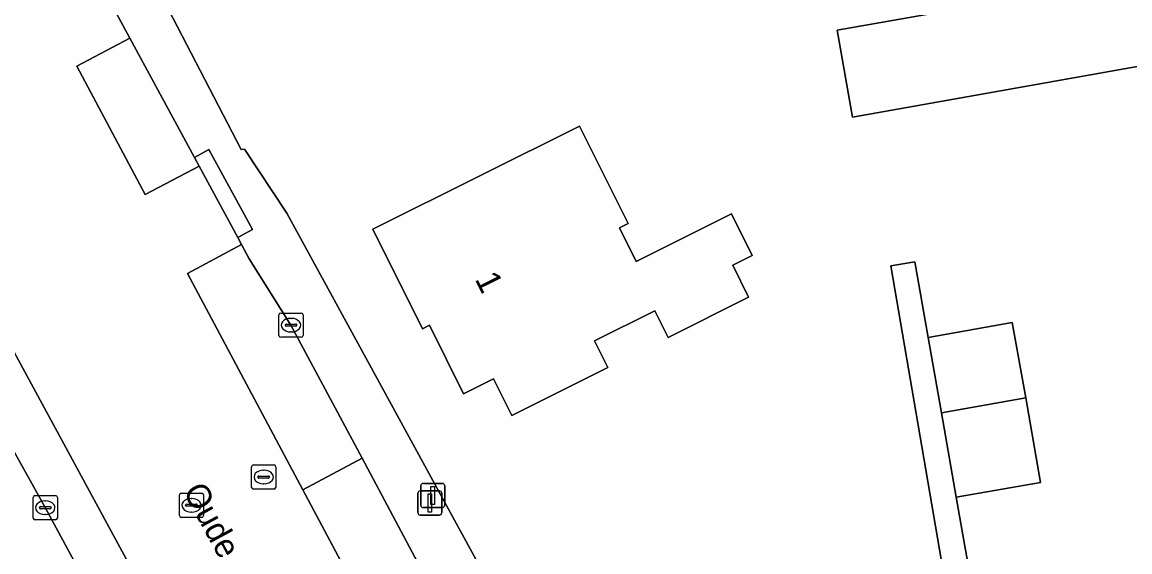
# Model space of a CAD drawing. Extents: x 162879 to 165540, y 384011 to 385181.
# Drawn here: x 164236.51 to 164282.3, y 384276.82 to 384298.69 of the extents above; entities that cross this region are included whole.
import ezdxf

# ---------------------------------------------------------------- set-up
doc = ezdxf.new("R2010")
doc.units = 0
for name, color, linetype in [('IMGEO_Erf', 7, 'Continuous'), ('IMGEO_Kolk', 7, 'Continuous'), ('IMGEO_Lichtmast', 7, 'Continuous'), ('IMGEO_Openbare_ruimte_label', 7, 'Continuous'), ('IMGEO_OVBaan_gesloten', 7, 'Continuous'), ('IMGEO_Pand', 7, 'Continuous'), ('IMGEO_Pand_nummerreeks', 7, 'Continuous'), ('IMGEO_Parkeervlak_gesloten', 7, 'Continuous'), ('IMGEO_Rijbaan_lokaal_gesloten', 7, 'Continuous'), ('IMGEO_Rioolput', 7, 'Continuous'), ('IMGEO_Voetpad_open', 7, 'Continuous')]:
    doc.layers.add(name, color=color, linetype=linetype)

msp = doc.modelspace()

# ---------------------------------------------------------------- linework, layer by layer
at = {"layer": 'IMGEO_Erf'}
for points in [[(164241.621, 384301.03), (164245.563, 384293.433), (164245.698, 384293.443), (164247.447, 384290.807), (164265.625, 384257.55), (164277.401, 384259.579), (164272.425, 384288.625), (164273.405, 384288.793), (164273.957, 384285.675), (164277.428, 384286.289), (164277.994, 384283.174), (164278.603, 384279.686), (164275.126, 384279.071), (164276.143, 384273.323), (164279.613, 384273.937), (164280.199, 384270.625), (164280.785, 384267.312), (164281.351, 384264.111), (164277.882, 384263.498), (164278.541, 384259.775), (164297.909, 384263.112)], [(164283.929, 384297.094), (164270.831, 384294.777), (164270.198, 384298.357), (164279.159, 384299.942)]]:
    msp.add_lwpolyline(points, dxfattribs=at)
msp.add_lwpolyline([(164259.556, 384294.396), (164261.556, 384290.377), (164261.197, 384290.198), (164261.886, 384288.812), (164265.832, 384290.775), (164266.687, 384289.057), (164265.882, 384288.656), (164266.542, 384287.33), (164263.209, 384285.672), (164262.659, 384286.776), (164260.171, 384285.538), (164260.723, 384284.431), (164256.747, 384282.452), (164255.994, 384283.965), (164254.753, 384283.347), (164253.346, 384286.175), (164253.059, 384286.033), (164251.013, 384290.145), (164255.481, 384292.369)], close=True, dxfattribs=at)
at = {"layer": 'IMGEO_Kolk'}
for p, q in [((164247.123, 384285.753), (164247.123, 384286.605)), ((164247.198, 384286.679), (164248.05, 384286.679)), ((164247.611, 384286.459), (164247.636, 384286.459)), ((164248.124, 384286.605), (164248.124, 384285.753)), ((164247.382, 384286.173), (164247.382, 384286.185)), ((164247.82, 384286.136), (164247.422, 384286.136)), ((164247.425, 384286.222), (164247.823, 384286.222)), ((164247.634, 384285.899), (164247.609, 384285.899)), ((164247.866, 384286.185), (164247.866, 384286.173)), ((164248.05, 384285.679), (164247.198, 384285.679)), ((164236.967, 384278.213), (164236.967, 384279.065)), ((164237.042, 384279.139), (164237.894, 384279.139)), ((164237.968, 384279.065), (164237.968, 384278.213)), ((164237.226, 384278.633), (164237.226, 384278.645)), ((164237.664, 384278.596), (164237.266, 384278.596)), ((164237.269, 384278.682), (164237.667, 384278.682)), ((164237.455, 384278.919), (164237.48, 384278.919)), ((164237.71, 384278.645), (164237.71, 384278.633)), ((164237.894, 384278.139), (164237.042, 384278.139)), ((164237.478, 384278.359), (164237.453, 384278.359))]:
    msp.add_line(p, q, dxfattribs=at)
for points in [[(164247.123, 384285.753), (164247.123, 384286.605)], [(164247.198, 384286.679), (164248.05, 384286.679)], [(164248.124, 384286.605), (164248.124, 384285.753)], [(164248.05, 384285.679), (164247.198, 384285.679)], [(164236.967, 384278.213), (164236.967, 384279.065)], [(164237.042, 384279.139), (164237.894, 384279.139)], [(164237.968, 384279.065), (164237.968, 384278.213)], [(164237.894, 384278.139), (164237.042, 384278.139)]]:
    msp.add_lwpolyline(points, dxfattribs=at)
for centre, radius, start, end in [((164247.2, 384286.603), 0.0765, 91.552, 178.448), ((164247.2, 384286.603), 0.0765, 91.552, 178.448), ((164248.048, 384286.603), 0.0765, 1.552, 88.448), ((164248.048, 384286.603), 0.0765, 1.552, 88.448), ((164247.422, 384286.182), 0.0403, 85.8775, 175.7526), ((164247.419, 384286.172), 0.0366, 178.938, 274.7102), ((164247.823, 384286.179), 0.043, 264.8664, 352.4533), ((164247.827, 384286.184), 0.0386, 1.7309, 96.639), ((164247.2, 384285.755), 0.0765, 181.552, 268.448), ((164247.2, 384285.755), 0.0765, 181.552, 268.448), ((164248.048, 384285.755), 0.0765, 271.552, 358.448), ((164248.048, 384285.755), 0.0765, 271.552, 358.448), ((164237.044, 384279.063), 0.0765, 91.552, 178.448), ((164237.044, 384279.063), 0.0765, 91.552, 178.448), ((164237.892, 384279.063), 0.0765, 1.552, 88.448), ((164237.892, 384279.063), 0.0765, 1.552, 88.448), ((164237.266, 384278.642), 0.0403, 85.8775, 175.7526), ((164237.263, 384278.632), 0.0366, 178.938, 274.7102), ((164237.667, 384278.639), 0.043, 264.8664, 352.4533), ((164237.671, 384278.644), 0.0386, 1.7309, 96.639), ((164237.044, 384278.215), 0.0765, 181.552, 268.448), ((164237.044, 384278.215), 0.0765, 181.552, 268.448), ((164237.892, 384278.215), 0.0765, 271.552, 358.448), ((164237.892, 384278.215), 0.0765, 271.552, 358.448)]:
    msp.add_arc(centre, radius, start, end, dxfattribs=at)
for centre, major_axis, ratio, start_param, end_param in [((164247.61, 384286.179), (-0.387, 0.002), 0.722429, 4.712389, 7.853982), ((164247.635, 384286.179), (-0.39, 0.002), 0.717154, 1.570796, 4.712389), ((164237.454, 384278.639), (-0.387, 0.002), 0.722429, 4.712389, 7.853982), ((164237.479, 384278.639), (-0.39, 0.002), 0.717154, 1.570796, 4.712389)]:
    msp.add_ellipse(centre, major_axis=major_axis, ratio=ratio, start_param=start_param, end_param=end_param, dxfattribs=at)
at = {"layer": 'IMGEO_Lichtmast'}
for p, q in [((164252.987, 384278.74), (164252.987, 384279.54)), ((164252.987, 384279.54), (164252.987, 384278.74)), ((164253.087, 384279.64), (164253.877, 384279.64)), ((164253.877, 384279.64), (164253.087, 384279.64)), ((164253.977, 384279.54), (164253.977, 384278.74)), ((164253.977, 384278.74), (164253.977, 384279.54)), ((164252.868, 384278.435), (164252.868, 384279.235)), ((164252.868, 384279.235), (164252.868, 384278.435)), ((164252.968, 384279.335), (164253.758, 384279.335)), ((164253.758, 384279.335), (164252.968, 384279.335)), ((164253.858, 384279.235), (164253.858, 384278.435)), ((164253.858, 384278.435), (164253.858, 384279.235)), ((164253.877, 384278.64), (164253.087, 384278.64)), ((164253.087, 384278.64), (164253.877, 384278.64)), ((164253.758, 384278.335), (164252.968, 384278.335)), ((164252.968, 384278.335), (164253.758, 384278.335))]:
    msp.add_line(p, q, dxfattribs=at)
for points in [[(164253.407, 384279.515), (164253.557, 384279.515), (164253.557, 384278.765), (164253.407, 384278.765), (164253.407, 384279.515)], [(164253.288, 384279.21), (164253.438, 384279.21), (164253.438, 384278.46), (164253.288, 384278.46), (164253.288, 384279.21)]]:
    msp.add_lwpolyline(points, dxfattribs=at)
for centre, start, end in [((164253.087, 384279.54), 90, 180), ((164253.087, 384279.54), 90, 180), ((164253.877, 384279.54), 0, 90), ((164253.877, 384279.54), 360, 90), ((164252.968, 384279.235), 90, 180), ((164252.968, 384279.235), 90, 180), ((164253.758, 384279.235), 0, 90), ((164253.758, 384279.235), 360, 90), ((164253.087, 384278.74), 180, 270), ((164253.087, 384278.74), 180, 270), ((164253.877, 384278.74), 270, 0), ((164253.877, 384278.74), 270, 0), ((164252.968, 384278.435), 180, 270), ((164252.968, 384278.435), 180, 270), ((164253.758, 384278.435), 270, 0), ((164253.758, 384278.435), 270, 0)]:
    msp.add_arc(centre, 0.1, start, end, dxfattribs=at)
at = {"layer": 'IMGEO_OVBaan_gesloten'}
msp.add_lwpolyline([(164250.573, 384280.685), (164248.108, 384279.38), (164259.664, 384257.72), (164269.773, 384244.273), (164268.442, 384246.955), (164266.854, 384250), (164265.912, 384251.805), (164255.842, 384270.772)], close=True, dxfattribs=at)
at = {"layer": 'IMGEO_Pand'}
for points in [[(164291.704, 384304.252), (164290.597, 384304.054), (164290.458, 384304.843), (164282.817, 384303.491), (164282.804, 384303.56), (164282.548, 384303.515), (164282.557, 384303.466), (164278.658, 384302.776), (164279.159, 384299.942), (164270.198, 384298.357), (164270.831, 384294.777), (164283.929, 384297.094), (164291.589, 384298.449), (164291.159, 384300.88), (164292.271, 384301.071)], [(164255.481, 384292.369), (164251.013, 384290.145), (164253.059, 384286.033), (164253.346, 384286.175), (164254.753, 384283.347), (164255.994, 384283.965), (164256.747, 384282.452), (164260.723, 384284.431), (164260.171, 384285.538), (164262.659, 384286.776), (164263.209, 384285.672), (164266.542, 384287.33), (164265.882, 384288.656), (164266.687, 384289.057), (164265.832, 384290.775), (164261.886, 384288.812), (164261.197, 384290.198), (164261.556, 384290.377), (164259.556, 384294.396)], [(164277.428, 384286.289), (164273.957, 384285.675), (164274.509, 384282.558), (164277.994, 384283.174)], [(164277.994, 384283.174), (164274.509, 384282.558), (164275.126, 384279.071), (164278.603, 384279.686)]]:
    msp.add_lwpolyline(points, close=True, dxfattribs=at)
at = {"layer": 'IMGEO_Parkeervlak_gesloten'}
for points in [[(164240.968, 384298.04), (164238.772, 384296.879), (164241.598, 384291.582), (164243.824, 384292.753), (164243.635, 384293.103)], [(164247.624, 384286.179), (164245.892, 384288.924), (164245.577, 384289.508), (164243.342, 384288.314), (164248.108, 384279.38), (164250.573, 384280.685)]]:
    msp.add_lwpolyline(points, close=True, dxfattribs=at)
msp.add_lwpolyline([(164229.138, 384293.772), (164232.524, 384287.484), (164237.469, 384278.64), (164246.74, 384261.507), (164248.74, 384257.903), (164249.04, 384257.338), (164250.722, 384258.259), (164229.396, 384297.567)], dxfattribs=at)
at = {"layer": 'IMGEO_Rijbaan_lokaal_gesloten'}
for points in [[(164238.643, 384301.819), (164237.023, 384302.288), (164236.356, 384302.626), (164236.139, 384302.83), (164228.566, 384298.705), (164229.396, 384297.567), (164250.722, 384258.259), (164249.04, 384257.338), (164251.111, 384253.429), (164252.95, 384250), (164254.686, 384246.762), (164256.229, 384243.947)], [(164269.773, 384244.273), (164259.664, 384257.72), (164248.108, 384279.38), (164243.342, 384288.314), (164245.577, 384289.508), (164245.423, 384289.793), (164243.824, 384292.753), (164241.598, 384291.582), (164238.772, 384296.879), (164240.968, 384298.04), (164239.944, 384299.935), (164239.208, 384301.296)]]:
    msp.add_lwpolyline(points, dxfattribs=at)
at = {"layer": 'IMGEO_Rioolput'}
for p, q in [((164246.073, 384280.404), (164246.925, 384280.404)), ((164245.998, 384279.478), (164245.998, 384280.33)), ((164246.257, 384279.898), (164246.257, 384279.91)), ((164246.3, 384279.947), (164246.698, 384279.947)), ((164246.486, 384280.184), (164246.511, 384280.184)), ((164246.741, 384279.91), (164246.741, 384279.898)), ((164246.999, 384280.33), (164246.999, 384279.478)), ((164246.695, 384279.861), (164246.297, 384279.861)), ((164246.509, 384279.624), (164246.484, 384279.624)), ((164243.011, 384278.312), (164243.011, 384279.164)), ((164243.086, 384279.238), (164243.938, 384279.238)), ((164243.499, 384279.018), (164243.524, 384279.018)), ((164244.012, 384279.164), (164244.012, 384278.312)), ((164246.925, 384279.404), (164246.073, 384279.404)), ((164243.27, 384278.732), (164243.27, 384278.744)), ((164243.708, 384278.695), (164243.31, 384278.695)), ((164243.313, 384278.781), (164243.711, 384278.781)), ((164243.754, 384278.744), (164243.754, 384278.732)), ((164243.938, 384278.238), (164243.086, 384278.238)), ((164243.522, 384278.458), (164243.497, 384278.458))]:
    msp.add_line(p, q, dxfattribs=at)
for points in [[(164246.073, 384280.404), (164246.925, 384280.404)], [(164245.998, 384279.478), (164245.998, 384280.33)], [(164246.999, 384280.33), (164246.999, 384279.478)], [(164243.011, 384278.312), (164243.011, 384279.164)], [(164243.086, 384279.238), (164243.938, 384279.238)], [(164244.012, 384279.164), (164244.012, 384278.312)], [(164246.925, 384279.404), (164246.073, 384279.404)], [(164243.938, 384278.238), (164243.086, 384278.238)]]:
    msp.add_lwpolyline(points, dxfattribs=at)
for centre, radius, start, end in [((164246.075, 384280.328), 0.0765, 91.552, 178.448), ((164246.075, 384280.328), 0.0765, 91.552, 178.448), ((164246.923, 384280.328), 0.0765, 1.552, 88.448), ((164246.923, 384280.328), 0.0765, 1.552, 88.448), ((164246.297, 384279.907), 0.0403, 85.8775, 175.7526), ((164246.294, 384279.897), 0.0366, 178.938, 274.7102), ((164246.698, 384279.904), 0.043, 264.8664, 352.4533), ((164246.702, 384279.909), 0.0386, 1.7309, 96.639), ((164246.075, 384279.48), 0.0765, 181.552, 268.448), ((164246.075, 384279.48), 0.0765, 181.552, 268.448), ((164246.923, 384279.48), 0.0765, 271.552, 358.448), ((164246.923, 384279.48), 0.0765, 271.552, 358.448), ((164243.088, 384279.162), 0.0765, 91.552, 178.448), ((164243.088, 384279.162), 0.0765, 91.552, 178.448), ((164243.936, 384279.162), 0.0765, 1.552, 88.448), ((164243.936, 384279.162), 0.0765, 1.552, 88.448), ((164243.31, 384278.741), 0.0403, 85.8775, 175.7526), ((164243.307, 384278.731), 0.0366, 178.938, 274.7102), ((164243.711, 384278.738), 0.043, 264.8664, 352.4533), ((164243.715, 384278.743), 0.0386, 1.7309, 96.639), ((164243.088, 384278.314), 0.0765, 181.552, 268.448), ((164243.088, 384278.314), 0.0765, 181.552, 268.448), ((164243.936, 384278.314), 0.0765, 271.552, 358.448), ((164243.936, 384278.314), 0.0765, 271.552, 358.448)]:
    msp.add_arc(centre, radius, start, end, dxfattribs=at)
for centre, major_axis, ratio, start_param, end_param in [((164246.485, 384279.904), (-0.387, 0.002), 0.722429, 4.712389, 7.853982), ((164246.51, 384279.904), (-0.39, 0.002), 0.717154, 1.570796, 4.712389), ((164243.498, 384278.738), (-0.387, 0.002), 0.722429, 4.712389, 7.853982), ((164243.523, 384278.738), (-0.39, 0.002), 0.717154, 1.570796, 4.712389)]:
    msp.add_ellipse(centre, major_axis=major_axis, ratio=ratio, start_param=start_param, end_param=end_param, dxfattribs=at)
at = {"layer": 'IMGEO_Voetpad_open'}
for points in [[(164265.625, 384257.55), (164247.447, 384290.807), (164245.698, 384293.443), (164245.563, 384293.433), (164241.621, 384301.03), (164239.944, 384299.935), (164240.968, 384298.04), (164243.635, 384293.103), (164244.235, 384293.431), (164246.037, 384290.128), (164245.423, 384289.793), (164245.577, 384289.508), (164245.892, 384288.924), (164247.624, 384286.179), (164250.573, 384280.685), (164255.842, 384270.772), (164265.912, 384251.805), (164266.854, 384250), (164268.442, 384246.955), (164269.773, 384244.273)], [(164229.396, 384297.567), (164222.041, 384294.537), (164224.051, 384287.357), (164226.385, 384288.011), (164228.859, 384283.61), (164229.599, 384282.486), (164230.627, 384280.926), (164232.261, 384281.94), (164233.682, 384279.119), (164234.844, 384279.704), (164236.057, 384277.336), (164234.879, 384276.743), (164236.057, 384274.403), (164237.404, 384274.205), (164238.833, 384271.815), (164246.887, 384256.909), (164248.74, 384257.903), (164246.74, 384261.507), (164237.469, 384278.64), (164232.524, 384287.484)]]:
    msp.add_lwpolyline(points, dxfattribs=at)
for points in [[(164244.235, 384293.431), (164243.635, 384293.103), (164243.824, 384292.753), (164245.423, 384289.793), (164246.037, 384290.128)], [(164275.126, 384279.071), (164274.509, 384282.558), (164273.957, 384285.675), (164273.405, 384288.793), (164272.425, 384288.625), (164277.401, 384259.579), (164278.541, 384259.775), (164277.882, 384263.498), (164277.316, 384266.698), (164276.73, 384270.011), (164276.143, 384273.323)]]:
    msp.add_lwpolyline(points, close=True, dxfattribs=at)

# ---------------------------------------------------------------- texts
at = {"layer": 'IMGEO_Openbare_ruimte_label'}
msp.add_text('Oude Urkhovenseweg', height=1, rotation=298.487, dxfattribs=at).set_placement((164243.145, 384279.326))
at = {"layer": 'IMGEO_Pand_nummerreeks'}
msp.add_text('1', height=1, rotation=296.4515, dxfattribs=at).set_placement((164255.211, 384288.085))

doc.saveas('drawing.dxf')
